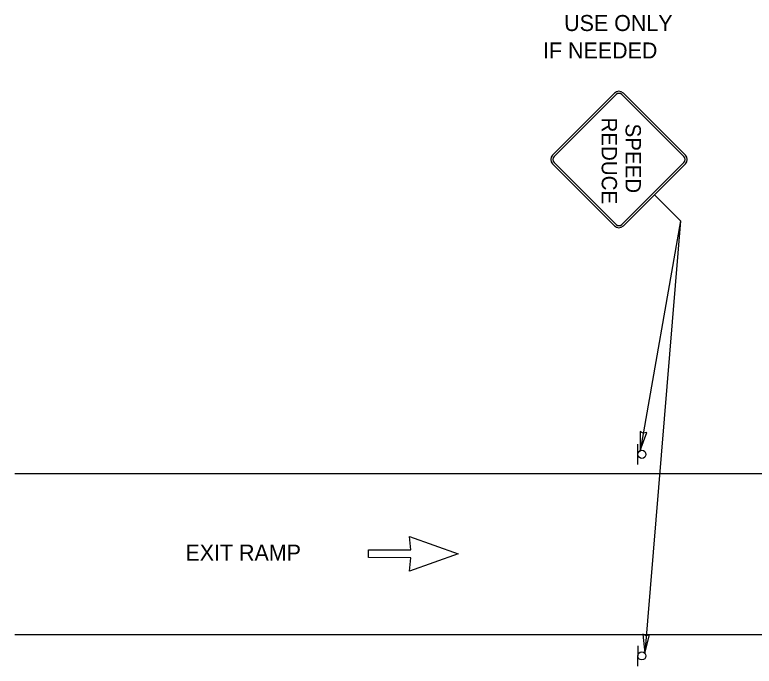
# Model space of a CAD drawing. Extents: x 46672 to 47298, y 5424 to 5742.
# Drawn here: x 47010.2 to 47139.3, y 5623.1 to 5736.9 of the extents above; entities that cross this region are included whole.
import ezdxf

# ---------------------------------------------------------------- set-up
doc = ezdxf.new("R2010")
doc.units = 0
for name, color, linetype in [('LaneDirArrow', 7, 'Continuous'), ('LeaderLine_dp', 7, 'Continuous'), ('RoadwayMisc', 7, 'Continuous'), ('SignPanel', 7, 'Continuous'), ('SignSupport', 7, 'Continuous'), ('TextLabel', 7, 'Continuous')]:
    doc.layers.add(name, color=color, linetype=linetype)

msp = doc.modelspace()

# ---------------------------------------------------------------- linework, layer by layer
at = {"layer": 'LaneDirArrow'}
for p, q in [((47079.33, 5643.4), (47079.09, 5645.74)), ((47079.09, 5645.74), (47087.58, 5642.7)), ((47071.9, 5642.04), (47071.91, 5643.42)), ((47071.91, 5643.42), (47079.33, 5643.4)), ((47079.33, 5642.03), (47071.9, 5642.04)), ((47087.58, 5642.7), (47079.08, 5639.69)), ((47079.08, 5639.69), (47079.33, 5642.03))]:
    msp.add_line(p, q, dxfattribs=at)
at = {"layer": 'LeaderLine_dp'}
for q in [(47121.85, 5705.42), (47119.36, 5660.72), (47120.15, 5625.36)]:
    msp.add_line((47126.4, 5700.87), q, dxfattribs=at)
for points in [[(47119.39, 5660.79), (47120.51, 5663.92), (47119.91, 5663.78), (47119.38, 5664.11)], [(47120.15, 5625.36), (47120.98, 5628.58), (47120.4, 5628.39), (47119.84, 5628.67)]]:
    msp.add_lwpolyline(points, close=True, dxfattribs=at)
at = {"layer": 'RoadwayMisc'}
for p, q in [((47010.15, 5656.76), (47280.21, 5656.76)), ((47010.15, 5628.64), (47280.21, 5628.64))]:
    msp.add_line(p, q, dxfattribs=at)
at = {"layer": 'SignPanel'}
for p, q in [((47104.06, 5712.38), (47114.89, 5723.21)), ((47104.32, 5712.13), (47115.15, 5722.95)), ((47116.18, 5722.95), (47127.01, 5712.13)), ((47116.44, 5723.21), (47127.26, 5712.38)), ((47114.89, 5700.01), (47104.06, 5710.84)), ((47115.15, 5700.27), (47104.32, 5711.09)), ((47127.01, 5711.09), (47116.18, 5700.27)), ((47127.26, 5710.84), (47116.44, 5700.01))]:
    msp.add_line(p, q, dxfattribs=at)
for centre, radius, start, end in [((47115.66, 5722.44), 1.09, 45, 135), ((47115.66, 5722.44), 0.729, 45, 135), ((47104.83, 5711.61), 1.09, 135, 225), ((47104.83, 5711.61), 0.729, 135, 225), ((47126.49, 5711.61), 0.729, 315, 45), ((47126.49, 5711.61), 1.09, 315, 45), ((47115.66, 5700.78), 1.09, 225, 315), ((47115.66, 5700.78), 0.729, 225, 315)]:
    msp.add_arc(centre, radius, start, end, dxfattribs=at)
at = {"layer": 'SignSupport'}
for p, q in [((47118.95, 5658.33), (47118.95, 5661.88)), ((47118.93, 5626.62), (47118.92, 5623.07))]:
    msp.add_line(p, q, dxfattribs=at)
for centre in [(47119.67, 5660.09), (47119.65, 5624.87)]:
    msp.add_circle(centre, 0.703, dxfattribs=at)

# ---------------------------------------------------------------- texts
at = {"layer": 'SignPanel'}
for s, p in [('REDUCE', (47112.64, 5718.94)), ('SPEED', (47116.81, 5717.89))]:
    msp.add_text(s, height=2.68, rotation=270, dxfattribs=at).set_placement(p)
at = {"layer": 'TextLabel'}
for s, p in [('USE ONLY', (47106.09, 5734.06)), ('IF NEEDED', (47102.39, 5729.26)), ('EXIT RAMP', (47039.95, 5641.52))]:
    msp.add_text(s, height=2.8, dxfattribs=at).set_placement(p)

doc.saveas('drawing.dxf')
